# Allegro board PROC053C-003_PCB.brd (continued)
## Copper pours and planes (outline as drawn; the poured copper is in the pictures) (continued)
VUSB_VBUS2 on TOP: 8.94,34.24 8.13,35.05 8.13,40.06 7.26,40.92 6.71,40.92 6.71,41.33 7.11,41.74 8.38,41.74 8.64,41.48 8.64,40.98 9.02,40.59 10.46,40.59 11.45,39.61 16.61,39.61 17.78,38.44 19.56,38.44 19.81,38.69 19.81,40.59 20.07,40.85 24.4,40.85 26.09,39.17 26.09,37.92 24.51,36.35 23.75,36.35 23,35.6 23,35.07 22.17,34.24
VUSB_VBUS2 on BOTTOM: 3.43,39.96 9.78,39.96 10.03,39.71 10.03,37.67 9.78,37.42 8.51,37.42 7.24,38.69 5.84,38.69 4.95,39.58 3.43,39.58
N11220684 on TOP: 108.8,15.81 109.9,15.81 110.27,15.44 110.27,13.58 110.38,13.47 110.89,13.47 110.98,13.56 110.98,16.6 110.76,16.81 108.97,16.81 108.77,16.61 108.77,15.84
N12225158 on L3_SIG1: 26.54,100.54 28.53,100.54 31.58,97.49 33.27,97.49 33.91,96.86 33.91,96.22 33.27,95.59 24.54,95.59 24.21,95.92 24.21,98.2
N16839102 on BOTTOM: 188.8,74.73 188.98,74.55 188.98,72.34 186.82,70.19 185.93,70.19 185.93,71.87 184.45,73.35 184.45,74.73
N17594977 on L3_SIG1: 27.2,83.16 34.11,83.16 35.64,81.64 35.64,78.47 34.92,77.75 24.92,77.75 24.21,78.47 24.21,80.17
N17596823 on L3_SIG1: 26.03,58.76 32.29,58.76 35.64,55.41 35.64,53.88 35.26,53.5 34.37,53.5 33.6,54.26 24.59,54.26 24.21,54.64 24.21,56.93
N17597002 on BOTTOM: 4.01,56.59 4.01,54.69 4.78,53.92 8.05,53.92 8.36,54.23 8.36,56.13 7.9,56.59
N19923823 on BOTTOM: 110.01,92.48 110.95,92.48 111.12,92.31 111.12,91.6 110.85,91.32 110.13,91.32 109.86,91.6 109.86,92.33
N19923823 on L4_SIG2: 107.21,86.16 109.5,86.16 110.11,86.77 110.11,93.17 110.36,93.43 111.25,93.43 111.48,93.2 111.48,85.63 110.19,84.33 107.11,84.33 106.71,84.74 106.71,85.65
N19923823 on L10_SIG4: 109.92,91.33 109.92,93.11 110.17,93.36 110.68,93.36 110.81,93.24 110.81,91.46 110.55,91.2 110.05,91.2
N19923824 on L4_SIG2: 107.34,86.42 108.86,86.42 109.65,87.2 109.65,92.74 109.22,93.17 108.58,93.17 107.98,92.56 107.98,87.36 107.75,87.13 107.44,87.13 107.21,86.9 107.21,86.54
N19923824 on L10_SIG4: 108.39,91.08 108.39,92.85 108.65,93.11 109.16,93.11 109.28,92.98 109.28,91.2 109.03,90.95 108.52,90.95
N19923831 on BOTTOM: 118.67,77.8 118.67,76.94 118.44,76.71 117.98,76.71 117.73,76.97 117.73,77.85 117.86,77.98 118.49,77.98
N19923831 on L5_GND2: 106.63,77.86 119.13,77.86 119.43,77.55 119.43,77.12 119.2,76.89 114.1,76.89 113.59,76.38 111.61,76.38 111.1,76.89 106.6,76.89 106.38,77.12 106.38,77.6
N19923831 on L10_SIG4: 118.11,78.44 119.38,78.44 119.76,78.06 119.76,77.45 119.28,76.97 118.44,76.97 117.73,77.68 117.73,78.06
N19923833 on L4_SIG2: 106.4,86.47 106.91,86.47 107.29,86.85 107.29,87.05 107.59,87.36 107.62,87.36 107.62,92.61 107.06,93.17 106.55,93.17 106.3,92.92 106.3,89.24 105.61,88.55 105.61,87.51 106.3,86.82 106.3,86.57
N19923833 on L10_SIG4: 106.17,91.01 106.17,92.79 106.43,93.05 106.93,93.05 107.06,92.92 107.06,91.14 106.81,90.89 106.3,90.89
N19923834 on BOTTOM: 114.68,73.66 115.32,73.66 115.44,73.53 115.44,72.52 115.19,72.26 114.55,72.26 114.3,72.52 114.3,73.28
N19923834 on L7_PWR2: 107.21,77.7 108.08,77.7 108.74,77.04 113.39,77.04 115.09,75.34 115.09,74.05 114.78,73.74 114.33,73.74 111.99,76.08 107.99,76.08 107.04,77.03 107.04,77.53
N19923834 on L10_SIG4: 114.15,74.99 115.09,74.99 115.39,74.68 115.39,72.47 115.19,72.26 114.43,72.26 113.94,72.75 113.94,74.78
N19923844 on L4_SIG2: 106.05,86.57 106.05,86.67 105.54,87.18 105.54,91.78 104.39,92.92 103.89,92.92 103.61,92.64 103.61,86.26 103.89,85.98 105.46,85.98
N19923844 on L10_SIG4: 103.76,92.54 104.14,92.92 104.52,92.92 104.9,92.54 104.9,91.27 104.52,90.89 104.27,90.89 103.76,91.39
N19923846 on L3_SIG1: 102.87,76.66 102.87,71.07 103.63,70.31 103.63,69.68 103.38,69.42 102.49,69.42 102.11,69.8 102.11,75.65 101.09,76.66 101.09,76.92 101.35,77.17 102.36,77.17
N19923850 on L10_SIG4: 88.8,84.38 90.53,84.38 91.03,83.88 91.03,83.32 90.98,83.27 89.15,83.27 88.65,83.77 88.65,84.23
N19923853 on L10_SIG4: 103.12,76.54 103.12,70.06 101.85,68.79 100.97,68.79 99.19,70.57 99.19,75.87 100.49,77.17 102.49,77.17
N20127658 on BOTTOM: 81.28,86.87 82.17,86.87 82.42,86.61 82.42,85.17 82.25,84.99 81.2,84.99 81.1,85.09 81.1,86.69
N20127658 on L9_SIG3: 84.96,80.52 91.31,80.52 91.82,81.03 91.82,82.17 87.25,86.74 82.93,86.74 82.42,86.23 82.42,83.06
N20127658 on L10_SIG4: 82.17,86.87 83.26,86.87 83.72,86.41 83.72,85.7 82.98,84.96 82.04,84.96 81.79,85.22 81.79,86.49
N20127658 on L10_SIG4: 88.17,83.14 90.17,83.14 90.68,82.63 90.68,82.61 90.07,82 89.65,82 89.66,81.99 88.65,81.99 88.01,82.63 88.01,82.98
N20128389 on BOTTOM: 95.76,83.06 96.01,83.06 96.14,83.19 96.14,83.44 95.25,84.33 92.84,84.33 92.33,84.84 92.33,86.11 94.23,88.01 94.23,95.38 95.5,96.65 95.5,97.28 95.31,97.48 91.83,97.48 91.66,97.31 91.66,92.99 92.86,91.8 92.86,88.29 91.44,86.87 91.44,83.82 91.95,83.31 95.5,83.31
N20287584 on TOP: 159.38,123.91 159.13,124.15 159.13,125.56 159.51,125.94 159.51,134.07 159.64,134.19 160.66,134.19 161.67,133.18 161.67,129.11 161.42,128.86 161.42,124.09 161.24,123.91
N20619479 on BOTTOM: 70.74,113.24 70.74,114 70.87,114.13 72.9,114.13 73.15,114.38 73.91,114.38 74.04,114.25 74.04,113.11 73.91,112.98 73.28,112.98 73.15,113.11 70.87,113.11
N20664562 on BOTTOM: 155.02,107.01 155.02,107.25 154.67,107.6 154.67,108.49 153.47,109.7 153.47,113.47 152.8,114.13 151.65,114.13 151.05,113.53 151.05,109.95 152.83,108.17 153.85,108.17 155.01,107.01
N20665027 on BOTTOM: 159.05,110.34 155.99,107.28 155.63,107.28 155.63,107.37 155.91,107.65 155.91,108.69 155.63,108.97 155.63,113.14 156.7,114.22 158.06,114.22 159.05,113.23
N21306347 on TOP: 154.18,99.14 154.43,98.89 154.43,97.36 154.31,97.24 153.04,97.24 152.91,97.36 152.91,97.74 152.4,98.25 148.34,98.25 147.96,98.63 147.96,98.89 148.21,99.14
N21552786 on BOTTOM: 157.99,56.52 157.99,54.48 158.12,54.36 161.04,54.36 161.16,54.48 161.16,54.86 160.78,55.24 159,55.24 158.75,55.5 158.75,56.52
N21605448 on TOP: 15.98,39.98 16.26,40.26 16.26,46.74 15.75,47.24 13.97,47.24 13.34,46.61 13.34,43.43 12.45,42.55 12.45,40.51 12.97,39.98
N21685968 on BOTTOM: 118.75,82.38 119.76,82.38 120.14,82 120.14,80.6 119.81,80.26 119.51,80.26 119,80.77 118.57,80.77 118.36,80.98 118.36,82
N21685968 on L7_PWR2: 106.55,83.14 118.24,83.14 118.62,82.76 118.62,82 118.36,81.74 106.55,81.74 106.3,82 106.3,82.89
N21685968 on L10_SIG4: 116.71,81.62 118.11,81.62 118.36,81.36 118.36,80.98 118.62,80.73 119.51,80.73 119.76,80.98 119.76,82.63 119.51,82.89 116.71,82.89 116.46,82.63 116.46,81.87
N22641301 on BOTTOM: 35.81,96.52 38.23,96.52 38.35,96.39 38.35,94.36 38.1,94.11 35.81,94.11 35.64,94.28 35.64,96.34
N22641309 on BOTTOM: 36.2,93.09 38.1,93.09 38.23,92.96 38.23,92.33 37.91,92.01 37.91,91 37.72,90.8 36.96,90.8 34.42,93.34 34.42,96.27 34.67,96.52 35.18,96.52 35.31,96.39 35.31,93.98
N22641383 on BOTTOM: 114.05,125.22 114.05,127.64 114.17,127.76 116.2,127.76 116.46,127.51 116.46,125.22 116.28,125.04 114.22,125.04
N22641391 on BOTTOM: 117.47,125.73 117.47,127.51 117.6,127.64 118.24,127.64 118.49,127.38 119.51,127.38 119.76,127.13 119.76,124.21 118.49,122.94 114.43,122.94 114.05,123.32 114.05,124.59 114.17,124.71 116.46,124.71

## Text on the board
BOTTOM: LAYER 12 BOTTOM SIDE | 12
Ref Des/Silkscreen Bottom: 2 | 1 | 7 | 8 | 9 | 5 | 4 | A1 | B1 | B2 | A2 | B17 | A17 | A18 | B18 | 59 | 60 | 3 | 29 | 24 | 23 | 30 | FID1 | FID4 | E | D | C | B | A | FID2 | FID3
TOP: LAYER 01 TOP SIDE | 1 | 12
Ref Des/Silkscreen Top: 1 | 2 | 5 | 3 | 4 | 29 | 24 | 30 | 23 | 7 | 8 | A2 | A1 | B2 | B1 | A18 | A17 | B17 | B18 | 5.0VDC | 4.0A | GND | PRU2 ETH1 | PRU2 ETH0 | PRU1ETH1 | PRU1ETH0 | Gb Ethernet0 | USB1 | Gb Ethernet1 | VDDS_DDR1 | HDMI | Profibus | VDD | VDD_MPU | VDD_DSPEVE | Expansion Connector | CAN | Warm | Hard | Reset | Power On | 8A Slow Blow | 125VAC, 125VDC | VMAIN | CAMERA | INDUSTRIAL LED0 | INDUSTRIAL LED1 | INDUSTRIAL LED2 | INDUSTRIAL LED3 | STATUS LED1 | STATUS LED0 | RS-485 | JTAG | USB JTAG | Industrial I/O | FID4 | FID1 | H | A | OPN# | PROJ# | S/N# | FID18 | PROC053 | REV C | C | B | G | D | F | E | J | FID2 | FID3 | PCIE | SD/MMC1 | FID19 | For evaluation only; not | FCC approved for resale
XSECTION_CHART: *  SURFACE - AIR 0 MIL | *  DIELECTRIC - TAIYO_4000_LDI 0.5 MIL | L1: TOP CONDUCTOR - COPPER 1.6 MIL | *  DIELECTRIC - 370H 3.8 MIL | L2: L2_GND1 PLANE - COPPER 1.3 MIL | *  DIELECTRIC - 370H 3.9 MIL | L3: L3_SIG1 CONDUCTOR - COPPER 1.7 MIL | *  DIELECTRIC - 370H 6.4 MIL | L4: L4_SIG2 CONDUCTOR - COPPER 0.6 MIL | *  DIELECTRIC - 370H 3.5 MIL | L5: L5_GND2 PLANE - COPPER 0.6 MIL | *  DIELECTRIC - 370H 4.8 MIL | L6: L6_PWR1 PLANE - COPPER 0.6 MIL | L7: L7_PWR2 PLANE - COPPER 0.6 MIL | L8: L8_GND3 PLANE - COPPER 0.6 MIL | L9: L9_SIG3 CONDUCTOR - COPPER 0.6 MIL | *  DIELECTRIC - 370H 6.6 MIL | L10: L10_SIG4 CONDUCTOR - COPPER 1.7 MIL | L11: L11_GND4 PLANE - COPPER 1.3 MIL | L12: BOTTOM CONDUCTOR - COPPER 1.6 MIL | DESIGN CROSS SECTION CHART | ___________________________ | TOTAL THICKNESS 62.3 MIL | 1-12 | 1-2 | 2-3 | 3-10 | 10-11 | 11-12
PAGE_OUTLINE: SILKSCREEN TOP | 1 | 2 | TI
DIMENSION: A | 1 | 2 | 7 | 8 | 12 | 9 | 5 | 14 | 4 | A1 | B1 | B2 | A2 | A17 | B17 | A18 | B18 | 59 | 60 | 3 | 29 | 24 | 23 | 30 | FID1 | FID4 | E | ASSEMBLY BOTTOM | D | C | B | FID3 | FID2 | +
DEVICE_TYPE_BOTTOM: 1 | 5 | 2 | 3 | 4 | 29 | 30 | 24 | 23 | 7 | 8 | A2 | A1 | B2 | B1 | A18 | A17 | B17 | B18 | FID4 | FID1 | H | ASSEMBLY TOP | A | C | B | G | D | F | E | J | FID3 | FID2 | * | Assembly Notes: | 1. These assemblies are ESD sensitive. | ESD precautians shall be observed. | 2. These assemblies must be clean and | free from flux and all contaminants. Use | of 'no clean flux' is not acceptable. | 3. These assemblies must comply with | workmanship standard IPC-A-610 Class 2, | unless otherwise specified. | 4. Each finished board will receive a | serial number sticker during final | testing. | 5. Each finished board will receive a | MAC Address sticker during final | 6. Install header shunt M1 (on J49) and | M2 (on J50) during final testing. | +
DISPLAY_BOTTOM: FABRICATION DRAWING | 1
User.8: LAYER 02 GND PLANE 1 | 2 | 12
User.9: LAYER 03 SIGNAL 1 | 3 | 12
User.10: LAYER 04 SIGNAL 2 | 4 | 12
User.11: LAYER 05 GND PLANE 2 | 5 | 12
User.12: SOLDER MASK BOTTOM | 2
User.13: SOLDER MASK TOP | 1 | 2
User.14: SOLDER PASTE BOTTOM | 2
User.15: SOLDER PASTE TOP | 1 | 2
User.16: SILKSCREEN BOTTOM | 2
User.18: LAYER 06 PWR SPLIT PLANE 1 | 6 | 12
User.19: LAYER 07 PWR SPLIT PLANE 2 | 7 | 12
User.20: ACTIVE AREA CENTER | LCD CONNECTOR LOCATION | LCD AND TS TOP VIEW
User.23: LAYER 08 GND PLANE 3 | 8 | 12
User.24: LAYER 09 SIGNAL 3 | 9 | 12
User.25: LAYER 10 SIGNAL 4 | 10 | 12
User.26: LAYER 11 GND PLANE 4 | 11 | 12
User.27: SELECTIVE PLATING TOP | 1
User.30: BOARD NAME: | BOARD NO: PROC053 | CUSTOMER NAME: | AM572X_INDUSTRIAL_EVM | TEXAS INSTRUMENTS | REV: C | DESCRIPTION: | DATE: 11/06/2019 | SH | OF
User.31: OF | SH | DATE:11/06/2019 | DESCRIPTION: | TEXAS INSTRUMENTS | REV:C | AM572X_INDUSTRIAL_EVM | BOARD NAME: | CUSTOMER NAME: | BOARD NO:PR0C053
User.32: L9_SIG3 | L1_TOP | L3_SIG1 | L4_SIG2 | L10_SIG4 | L12_BOTTOM | LAYERS | in mils | TRACE | WIDTH | 4.3 | 4.5 | 6.8 | +/-10% | TARGET | SINGLE-ENDED | Ohms | 50 | 4.2 | - | 60 | 5.9 | EDGE-COUPLED DIFFERENTIAL | SPACE | 7.7 | 6.1 | 90 | 3.25 | 4.25 | 3.9 | 8.75 | 8.1 | 5.75 | 100
User.35: IMPEDANCE REQUIREMENT :- THIS DESIGN MAY NOT CONTAIN ALL THE FEATURES | NOTE : | LISTED IN THE ABOVE TABLE | 10. DESIGN HAS INTENTIONAL SHORTS AT U95 COMPONENT AS SHOWN IN IPC356 NETLIST. | 11. ALL DRILLS TO HAVE POSITIONAL TOLERANCE OF +/- 3 MIL. | CLASS 2 AND WORKMANSHIP SHALL CONFORM TO | IPC-A-600, CLASS 2. CURRENT REVISIONS. | 2. THE PWB SHALL BE FABRICATED TO IPC-6012, | 9. ALL VIAS TO HAVE SOLDERMASK. FOLLOW AS PER THE ARTWORK. | 3. BOARD MATERIAL SHALL BE 180 Tg/350 Td ISOLA FR-370 HR | OR EQUIVALENT, RoHS COMPLIANT AND LEAD FREE | ASSEMBLY CAPABLE.  BOARD MATERIAL SHALL | MEET OR EXCEED IPC-4101B. COLOR: NATURAL. | 5. MINIMUM COPPER WALL THICKNESS OF PLATED-THRU | HOLES TO BE .001 INCH, WITH A MINIMUM | ANNULAR RING OF .002 INCH. | 4. BOARD MATERIAL & CONSTRUCTION TO BE UL94V0 CERTIFIED | AND MARKED ON TOP SIDE OF FINISHED BOARD. | FAB NOTES: | 6. OVERALL BOARD THICKNESS TO BE 0.0623" +/- 10% | AND APPLIES AFTER ALL LAMINATION AND PLATING | 1. ALL DIMENSIONS ARE IN INCHES, UNLESS | OTHERWISE NOTED. | SUPPLIED IPC-D-356 NETLIST. | PROCESSES, MEASURED FROM COPPER TO COPPER. | 8. BOARD MUST BE ELECTRICALLY TESTED USING | 7. MAX. WARP & TWIST TO BE .0075 INCHES PER INCH. | 2. APPLY LPI SOLDERMASK OVER BARE COPPER (SMOBC), | COLOR: BLACK SOLDERMASK SHALL | CONFORM TO IPC-SM-840, CLASS H. CURRENT REV. | 3. SOLDERMASK ARTWORK HAS ZERO (0) OVERSIZED PADS. | FABRICATION VENDOR IS ALLOWED TO ADJUST THE COMPONENT | SOLDERMASK PADS TO MEET THEIR TOOLING REQUIREMENTS. | 4. APPLY LPI SILKSCREEN OR EQUIVALENT PER THE ARTWORK. | 200uIN OF NICKEL. KNOOP HARDNESS 130-200. | B) SELECTIVE PLATING TO MIN 50uIN OF GOLD OVER 200uIN OF NICKEL. | KNOOP HARDNESS 130-200 PER ARTWORK SLPT (SELECTIVE PLATE TOP) | COLOR: WHITE. | 5. A) ALL CORE AND PREPREG THICKNESSES ARE UP TO FAB SHOP TO SELECT. | B) EXTERNAL LAYER CU THICKNESSES ARE FINISHED THICKNESS AFTER PLATING. | PROCESS NOTES: | 1. A) PLATE CIRCUITARY ON OUTER LAYERS TO 2-5uIN OF GOLD OVER
User.38: FIGURE | SIZE | 5.0 | 8.0 | DRILL CHART: L2_GND1 to L3_SIG1 | ALL UNITS ARE IN MILS | TOLERANCE | +0.0/-5.0 | +0.0/-8.0 | PLATED | QTY | 620 | 642
User.39: FIGURE | SIZE | 5.0 | 8.0 | DRILL CHART: TOP to L2_GND1 | ALL UNITS ARE IN MILS | TOLERANCE | +0.0/-5.0 | +0.0/-8.0 | PLATED | QTY | 620 | 642
User.42: FIGURE | SIZE | 8.0 | 10.0 | 28.0 | 28.35 | 30.0 | 33.0 | 35.04 | 40.0 | 40.16 | 43.0 | 45.0 | 45.28 | 50.0 | 67.0 | 68.9 | 90.0 | 120.0 | 140.0 | 33.46 | 59.0 | 92.52 | 125.98 | 138.0 | DRILL CHART: TOP to BOTTOM | ALL UNITS ARE IN MILS | TOLERANCE | +0.0/-8.0 | +0.0/-10.0 | +3.0/-3.0 | +2.0/-2.0 | PLATED | NON-PLATED | QTY | 1102 | 1677 | 9 | 36 | 2 | 60 | 52 | 47 | 54 | 4 | 24 | 6 | 12 | 1
User.43: FIGURE | SIZE | 5.0 | 8.0 | DRILL CHART: L11_GND4 to BOTTOM | ALL UNITS ARE IN MILS | TOLERANCE | +0.0/-5.0 | +0.0/-8.0 | PLATED | QTY | 389 | 423
User.44: FIGURE | SIZE | 8.0 | DRILL CHART: L3_SIG1 to L10_SIG4 | ALL UNITS ARE IN MILS | TOLERANCE | +0.0/-8.0 | PLATED | QTY | 918
User.45: FIGURE | SIZE | 5.0 | 8.0 | DRILL CHART: L10_SIG4 to L11_GND4 | ALL UNITS ARE IN MILS | TOLERANCE | +0.0/-5.0 | +0.0/-8.0 | PLATED | QTY | 390 | 422
